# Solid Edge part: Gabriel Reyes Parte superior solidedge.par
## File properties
Author: owner
Template: iso metric part.par
Last saved by: owner
Revision: 1
Application: Solid Edge
Precisión: 0.990
Username: owner
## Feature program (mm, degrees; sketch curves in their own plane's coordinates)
body "unnamed Body 1"
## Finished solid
Body 1: solid body, 319 faces, 1084 edges, 709 vertices.
  Faces by surface: plane 204, cylinder 97, sphere 8, spline 8, torus 2
  Edges by curve: line 873, circle 176, spline 27, ellipse 8
Bounding box of the edges (mm; curved faces can reach further): 87.700 x 107.000 x 49.840, from (-43.85, -107, 0) to (43.85, 0, 49.84).
Cylindrical faces by radius (mm): R1.4 x4, R1.5 x54, R2 x31, R2.6 x4, R95.8643 x2, R95.8646 x1, R95.8647 x1
Toroidal faces (ring radius, tube radius in mm): R94.3643 r1.5 x2
Spherical faces by radius (mm): R1.5 x8
Planar faces by outward normal: +x 39, +y 46, +z 7, -x 39, -y 46, -z 27
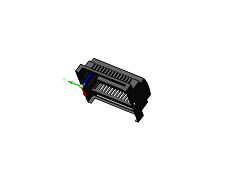
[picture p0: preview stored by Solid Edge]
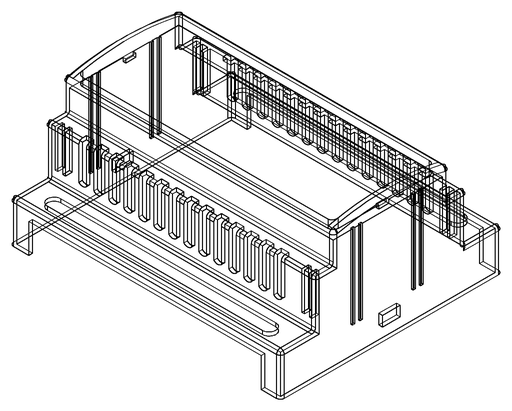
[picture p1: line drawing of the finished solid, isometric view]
